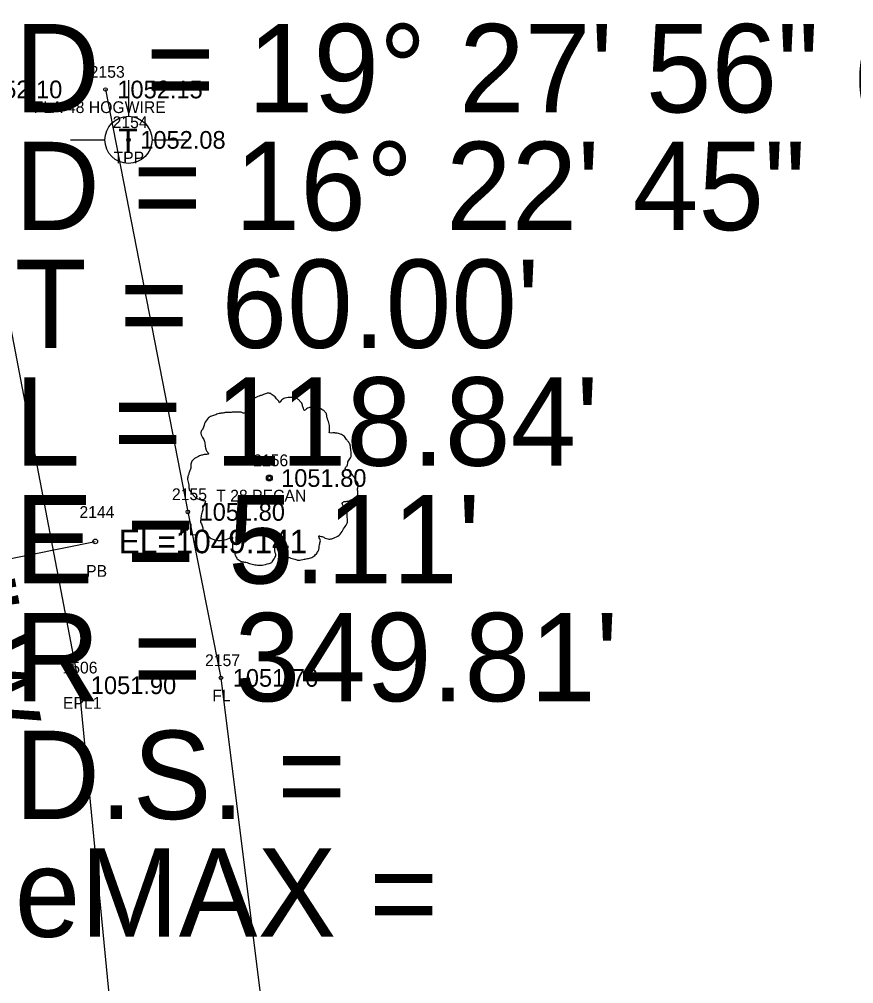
# Model space of a CAD drawing. Extents: x 1578957 to 1581675, y 1115963 to 1120391.
# Drawn here: x 1579799.4 to 1579870.3, y 1118068 to 1118149.9 of the extents above; entities that cross this region are included whole.
import ezdxf

# ---------------------------------------------------------------- set-up
doc = ezdxf.new("R2010")
doc.units = 0
for name, color, linetype in [('RD_EX_DR_Pipe', 7, 'Continuous'), ('RD_EX_DR_Pipe_txCode', 7, 'Continuous'), ('RD_EX_Fence_Other', 7, 'Continuous'), ('RD_EX_Fence_Other_txCode', 7, 'Continuous'), ('RD_EX_Road', 7, 'Continuous'), ('RD_EX_Road_txCode', 7, 'Continuous'), ('RD_EX_TX_Fence_Other_ELEV', 7, 'Continuous'), ('RD_EX_TX_Road_ELEV', 7, 'Continuous'), ('RD_EX_TX_UT_ELEV', 7, 'Continuous'), ('RD_EX_TX_VEG_ELEV', 7, 'Continuous'), ('RD_EX_UT', 7, 'Continuous'), ('RD_EX_UT_txCode', 7, 'Continuous'), ('RD_EX_VEG', 7, 'Continuous'), ('RD_EX_VEG_txCode', 7, 'Continuous'), ('RD_HC_Data', 7, 'Continuous'), ('RD_SMD_Locator', 7, 'Continuous'), ('RD_TX_Pipe_ElevEX', 7, 'Continuous')]:
    doc.layers.add(name, color=color, linetype=linetype)

msp = doc.modelspace()

# ---------------------------------------------------------------- linework, layer by layer
at = {"layer": 'RD_EX_DR_Pipe'}
msp.add_line((1579771.191, 1118098.59), (1579805.843, 1118105.564), dxfattribs=at)
at = {"layer": 'RD_EX_Fence_Other'}
msp.add_lwpolyline([(1579806.715, 1118143.937), (1579813.7, 1118108.075), (1579816.514, 1118093.983), (1579823.104, 1118041.087), (1579819.64, 1117977.762)], dxfattribs=at)
at = {"layer": 'RD_EX_Road'}
msp.add_lwpolyline([(1580132.914, 1117689.949), (1580126.197, 1117690.713), (1580104.514, 1117701.773), (1580054.231, 1117722.915), (1579999.655, 1117728.645), (1579947.034, 1117725.641), (1579902.617, 1117727.901), (1579859.282, 1117741.23), (1579828.335, 1117764.868), (1579804.422, 1117802.726), (1579793.197, 1117845.912), (1579792.758, 1117891.982), (1579799.628, 1117938.215), (1579807.414, 1117987.508), (1579809.684, 1118039.768), (1579804.464, 1118093.359), (1579794.793, 1118143.944)], dxfattribs=at)
at = {"layer": 'RD_EX_UT'}
for p, q in [((1579808.661, 1118144.731), (1579808.661, 1118141.661)), ((1579803.73, 1118139.676), (1579806.661, 1118139.676)), ((1579810.66, 1118139.676), (1579813.73, 1118139.676))]:
    msp.add_line(p, q, dxfattribs=at)
msp.add_circle((1579808.661, 1118139.661), 2, dxfattribs=at)
at = {"layer": 'RD_EX_VEG'}
for centre, radius in [((1579820.623, 1118110.954), 0.25), ((1579820.61, 1118110.935), 0.0001)]:
    msp.add_circle(centre, radius, dxfattribs=at)
for points in [[(1579820.755, 1118118.121), (1579820.455, 1118118.146), (1579820.13, 1118118.046), (1579819.88, 1118117.946), (1579819.655, 1118117.871), (1579819.43, 1118117.771), (1579819.13, 1118117.596), (1579818.905, 1118117.397), (1579818.78, 1118117.147), (1579818.73, 1118116.922), (1579818.68, 1118116.647), (1579818.68, 1118116.472), (1579818.556, 1118116.447), (1579818.406, 1118116.472), (1579818.156, 1118116.547), (1579817.906, 1118116.547), (1579817.656, 1118116.547), (1579817.306, 1118116.522), (1579816.956, 1118116.522), (1579816.681, 1118116.472), (1579816.356, 1118116.422), (1579815.982, 1118116.297), (1579815.632, 1118116.172), (1579815.332, 1118115.922), (1579815.082, 1118115.447), (1579814.957, 1118115.098), (1579814.807, 1118114.848), (1579814.957, 1118114.398), (1579815.132, 1118114.048), (1579815.157, 1118113.848), (1579815.232, 1118113.423), (1579815.332, 1118113.198), (1579815.457, 1118112.998), (1579815.382, 1118112.974), (1579815.007, 1118112.924), (1579814.707, 1118112.824), (1579814.282, 1118112.599), (1579814.057, 1118112.374), (1579813.957, 1118112.049), (1579813.933, 1118111.699), (1579813.833, 1118111.499), (1579813.758, 1118111.224), (1579813.733, 1118111.149), (1579813.683, 1118110.824), (1579813.783, 1118110.375), (1579813.808, 1118110.025), (1579813.933, 1118109.8), (1579814.082, 1118109.625), (1579814.257, 1118109.375), (1579814.657, 1118109.15), (1579814.982, 1118109.05), (1579815.182, 1118109.025), (1579815.007, 1118108.525), (1579814.957, 1118108.176), (1579814.832, 1118107.776), (1579814.832, 1118107.701), (1579814.782, 1118107.226), (1579814.932, 1118106.901), (1579815.007, 1118106.526), (1579815.182, 1118106.301), (1579815.457, 1118106.002), (1579815.782, 1118105.777), (1579816.282, 1118105.652), (1579816.681, 1118105.677), (1579817.256, 1118105.852), (1579817.506, 1118105.927), (1579817.481, 1118105.752), (1579817.506, 1118105.377), (1579817.506, 1118104.952), (1579817.656, 1118104.627), (1579817.756, 1118104.352), (1579817.906, 1118104.102), (1579818.231, 1118103.877), (1579818.63, 1118103.802), (1579819.055, 1118103.653), (1579819.505, 1118103.578), (1579820.005, 1118103.553), (1579820.605, 1118103.702), (1579820.879, 1118103.827), (1579820.979, 1118104.002), (1579821.179, 1118104.377), (1579821.129, 1118104.602), (1579821.154, 1118105.202), (1579821.254, 1118105.027), (1579821.429, 1118104.677), (1579821.929, 1118104.377), (1579822.329, 1118104.202), (1579822.804, 1118104.052), (1579823.104, 1118103.977), (1579823.578, 1118104.052), (1579823.953, 1118104.127), (1579824.328, 1118104.252), (1579824.628, 1118104.527), (1579824.803, 1118104.802), (1579824.853, 1118105.077), (1579824.928, 1118105.452), (1579824.978, 1118105.627)], [(1579824.978, 1118105.627), (1579824.903, 1118105.802), (1579824.853, 1118106.052), (1579824.928, 1118106.026), (1579825.103, 1118105.976), (1579825.378, 1118105.852), (1579825.602, 1118105.777), (1579825.927, 1118105.802), (1579826.202, 1118105.902), (1579826.652, 1118106.177), (1579826.927, 1118106.651), (1579827.202, 1118107.051), (1579827.277, 1118107.376), (1579827.227, 1118107.601), (1579827.202, 1118108.101), (1579827.002, 1118108.35), (1579826.952, 1118108.475), (1579826.852, 1118108.875), (1579826.927, 1118108.925), (1579827.202, 1118108.975), (1579827.577, 1118109.1), (1579827.851, 1118109.225), (1579828.076, 1118109.4), (1579828.151, 1118109.625), (1579828.126, 1118110.025), (1579828.176, 1118110.425), (1579828.101, 1118110.575), (1579828.001, 1118110.724), (1579827.926, 1118110.924), (1579827.776, 1118111.074), (1579827.677, 1118111.224), (1579827.577, 1118111.324), (1579827.452, 1118111.474), (1579827.277, 1118111.599), (1579827.127, 1118111.649), (1579827.077, 1118111.799), (1579827.227, 1118111.999), (1579827.277, 1118112.099), (1579827.302, 1118112.324), (1579827.527, 1118112.674), (1579827.577, 1118113.073), (1579827.527, 1118113.498), (1579827.477, 1118113.773), (1579827.327, 1118114.048), (1579827.127, 1118114.298), (1579827.002, 1118114.473), (1579826.827, 1118114.598), (1579826.502, 1118114.723), (1579826.252, 1118114.773), (1579825.902, 1118114.773), (1579825.702, 1118114.823), (1579825.727, 1118114.873), (1579825.727, 1118115.023), (1579825.727, 1118115.297), (1579825.652, 1118115.747), (1579825.502, 1118116.247), (1579825.502, 1118116.272), (1579825.402, 1118116.522), (1579825.178, 1118116.722), (1579825.003, 1118116.822), (1579824.803, 1118116.947), (1579824.553, 1118116.972), (1579824.253, 1118116.972), (1579823.978, 1118116.922), (1579823.778, 1118116.822), (1579823.603, 1118116.697), (1579823.528, 1118116.847), (1579823.428, 1118117.147), (1579823.378, 1118117.297), (1579823.228, 1118117.471), (1579823.004, 1118117.671), (1579822.554, 1118117.796), (1579821.929, 1118117.721), (1579821.629, 1118117.522), (1579821.479, 1118117.347), (1579821.429, 1118117.471), (1579821.229, 1118117.671), (1579821.129, 1118117.846), (1579820.954, 1118117.971), (1579820.805, 1118118.071), (1579820.705, 1118118.121)]]:
    msp.add_spline(points, degree=3, dxfattribs=at)
at = {"layer": 'RD_SMD_Locator'}
for centre, radius in [((1579806.715, 1118143.937), 0.15), ((1579808.661, 1118139.661), 0.15), ((1579820.623, 1118110.954), 0.15), ((1579813.7, 1118108.075), 0.15), ((1579805.843, 1118105.564), 0.2), ((1579804.464, 1118093.359), 0.15), ((1579816.514, 1118093.983), 0.15)]:
    msp.add_circle(centre, radius, dxfattribs=at)

# ---------------------------------------------------------------- texts
at = {"layer": 'RD_EX_DR_Pipe_txCode'}
for s, p in [('2144', (1579804.496, 1118107.564)), ('PB', (1579805.063, 1118102.564))]:
    msp.add_text(s, height=1, dxfattribs=at).set_placement(p)
at = {"layer": 'RD_EX_Fence_Other_txCode'}
for s, p in [('2153', (1579805.369, 1118144.937)), ('FLA 48 HOGWIRE', (1579800.609, 1118141.937)), ('2155', (1579812.354, 1118109.075)), ('FL', (1579812.968, 1118106.075)), ('2157', (1579815.167, 1118094.983)), ('FL', (1579815.781, 1118091.983))]:
    msp.add_text(s, height=1, dxfattribs=at).set_placement(p)
at = {"layer": 'RD_EX_Road_txCode'}
for s, p in [('1506', (1579803.055, 1118094.359)), ('EPL1', (1579803.094, 1118091.359))]:
    msp.add_text(s, height=1, dxfattribs=at).set_placement(p)
at = {"layer": 'RD_EX_TX_Fence_Other_ELEV'}
for s, p in [('1052.15', (1579807.715, 1118143.187)), ('1051.80', (1579814.7, 1118107.325)), ('1051.76', (1579817.514, 1118093.233))]:
    msp.add_text(s, height=1.5, dxfattribs=at).set_placement(p)
at = {"layer": 'RD_EX_TX_Road_ELEV'}
for s, p in [('1052.10', (1579795.793, 1118143.194)), ('1051.90', (1579805.464, 1118092.609))]:
    msp.add_text(s, height=1.5, dxfattribs=at).set_placement(p)
at = {"layer": 'RD_EX_TX_UT_ELEV'}
msp.add_text('1052.08', height=1.5, dxfattribs=at).set_placement((1579809.661, 1118138.911))
at = {"layer": 'RD_EX_TX_VEG_ELEV'}
msp.add_text('1051.80', height=1.5, dxfattribs=at).set_placement((1579821.623, 1118110.204))
at = {"layer": 'RD_EX_UT'}
msp.add_text('T', height=2, dxfattribs=at).set_placement((1579807.811, 1118138.614))
at = {"layer": 'RD_EX_UT_txCode'}
for s, p in [('2154', (1579807.314, 1118140.661)), ('TPP', (1579807.393, 1118137.661))]:
    msp.add_text(s, height=1, dxfattribs=at).set_placement(p)
at = {"layer": 'RD_EX_VEG_txCode'}
for s, p in [('2156', (1579819.253, 1118111.954)), ('T 28 PECAN', (1579816.111, 1118108.954))]:
    msp.add_text(s, height=1, dxfattribs=at).set_placement(p)
at = {"layer": 'RD_HC_Data'}
for s, p in [('    = 19%%d 27\' 56" (LT)', (1579799, 1118142)), ('D', (1579799, 1118142)), ('D = 16%%d 22\' 45"', (1579799, 1118132)), ("T = 60.00'", (1579799, 1118122)), ("L = 118.84'", (1579799, 1118112)), ("E = 5.11'", (1579799, 1118102)), ("R = 349.81'", (1579799, 1118092)), ('D.S. = ', (1579799, 1118082)), ('eMAX = ', (1579799, 1118072))]:
    msp.add_text(s, height=7.5, dxfattribs=at).set_placement(p)
msp.add_text('N 10%%d 35\' 21" W', height=6, rotation=280.58909, dxfattribs=at).set_placement((1579784.963, 1118144.913))
at = {"layer": 'RD_TX_Pipe_ElevEX'}
msp.add_text('EL=1049.141', height=2, dxfattribs=at).set_placement((1579807.843, 1118104.564))

doc.saveas('drawing.dxf')
